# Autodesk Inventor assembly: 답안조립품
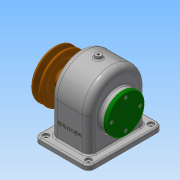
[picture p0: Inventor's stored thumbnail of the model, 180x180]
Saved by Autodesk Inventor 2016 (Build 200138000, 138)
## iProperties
Created: 2018-08
Part Number: 답안조립품
Material: 일반
Document SubType Name: Assembly
Designer: Administrator
Author: Administrator
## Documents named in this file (14)
- C:\Users\Administrator\Desktop\480811V1011\답안조립품.iam
- C:\Users\Administrator\Desktop\480811V1011\본체.ipt
- C:\Users\Administrator\Desktop\480811V1011\축.ipt
- C:\Users\Administrator\Desktop\480811V1011\베어링 6203.ipt
- C:\Users\Administrator\Desktop\480811V1011\스퍼기어.ipt
- C:\Users\Administrator\Desktop\480811V1011\키 6x6x22.ipt
- C:\Users\Administrator\Desktop\480811V1011\뒤커버.ipt
- C:\Users\Administrator\Desktop\480811V1011\볼트 M4.ipt
- C:\Users\Administrator\Desktop\480811V1011\앞커버.ipt
- C:\Users\Administrator\Desktop\480811V1011\부시.ipt
- C:\Users\Administrator\Desktop\480811V1011\오일 실 28 40 8.ipt
- C:\Users\Administrator\Desktop\480811V1011\키 5x5x18.ipt
- C:\Users\Administrator\Desktop\480811V1011\멈춤나사 M4.ipt
- C:\Users\Administrator\Desktop\480811V1011\V-벨트풀리.ipt
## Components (1 placed, 1 different names)
1. V-벨트풀리:1
